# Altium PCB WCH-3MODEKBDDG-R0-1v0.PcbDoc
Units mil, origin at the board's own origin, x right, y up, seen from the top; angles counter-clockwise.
Board outline 452.76 x 645.67 mil, 2 copper layers (Top Layer, Bottom Layer); 13 components, 13 nets, 62 pads, 34 vias.
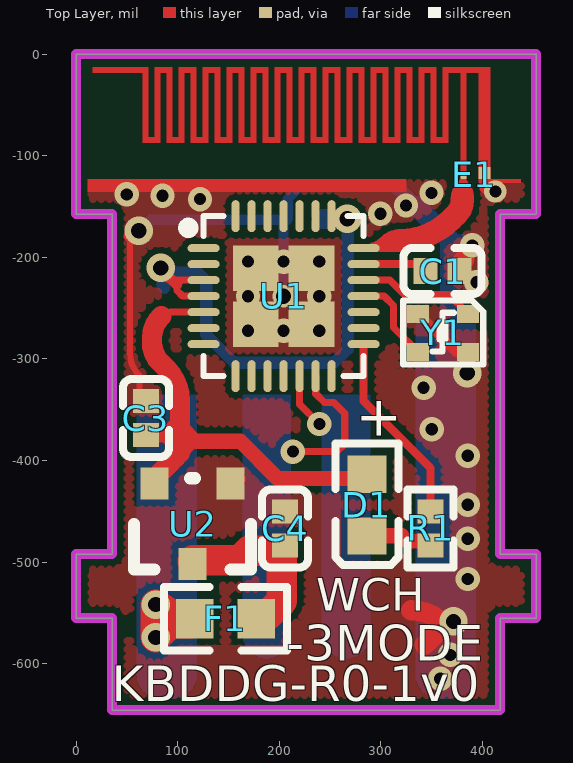
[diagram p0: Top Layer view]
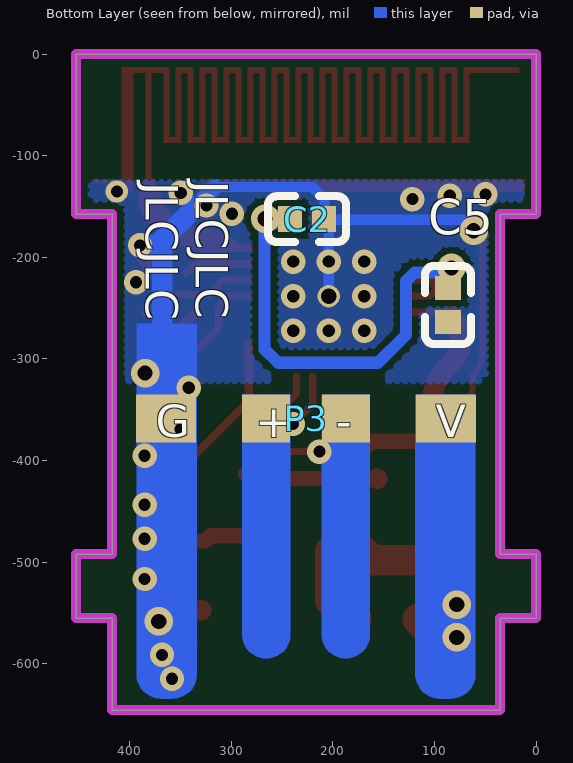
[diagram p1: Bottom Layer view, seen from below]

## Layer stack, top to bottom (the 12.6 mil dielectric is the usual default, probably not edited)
Top Solder: solder mask 0.4, Solder Resist, Dk 3.5
Top Layer: signal copper 1.4
Dielectric1: dielectric 12.6, FR-4, Dk 4.8
Bottom Layer: signal copper 1.4
Bottom Solder: solder mask 0.4, Solder Resist, Dk 3.5

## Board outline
0,-555.12 35.43,-555.12 35.43,-645.67 417.32,-645.67 417.32,-555.12 452.76,-555.12 452.76,-492.13 417.32,-492.13 417.32,-157.48 452.76,-157.48 452.76,0 0,0 0,-157.48 35.43,-157.48 35.43,-492.13 0,-492.13

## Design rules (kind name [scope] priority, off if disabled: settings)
Clearance [All] p1: gap=6 ignorepadtopadclearanceinfootprint=FALSE
ComponentClearance [All] p1 off: gap=10 collisioncheckmode=3 verticalgap=10 showdistances=FALSE
DiffPairsRouting [All] p1: maxlimit=15 minlimit=6 mostfreqgap=8 toplayer_minwidth=6 toplayer_maxwidth=15 toplayer_prefwidth=8 bottomlayer_minwidth=6 bottomlayer_maxwidth=15 bottomlayer_prefwidth=8 maxuncoupledlength=500
MinimumSolderMaskSliver [All] p1 off: minsoldermaskwidth=10
PolygonConnect [All] p1: connectstyle=Direct reliefconductorwidth=10 reliefentries=4 polygonreliefangle="90 Angle" airgapwidth=10
RoutingVias [All] p1: holewidth=28 width=50 viastyle="Through Hole" minholewidth=12 minwidth=24 maxholewidth=28 maxwidth=50
SilkToSilkClearance [All] p1 off: silktosilkclearance=10
SilkToSolderMaskClearance SilkscreenOverComponentPads [IsPad] p1 off: minsilkscreentomaskgap=10 clearancetoexposedcopper=TRUE
SolderMaskExpansion [All] p1: expansion=4 istentingtop=FALSE
Width [All] p1: maxlimit=50 minlimit=5.9 preferedwidth=10
25 further rules are at their usual default settings.

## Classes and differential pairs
differential pair NewDifferentialPair1: +PB10 -PB11

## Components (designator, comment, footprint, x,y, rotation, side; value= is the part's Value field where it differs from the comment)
C1 "2.2uF" 0402_C 377.43,-213.46 r270 top
C2 "0.1uF" 0402_C 208.8,-162.4 r270 bottom
C3 "0.1uF" 0402_C 68.7,-341.48 r0 top
C4 "2.2uF" 0402_C 205.58,-450.09 r0 top value=100pF
C5 "0.1uF" 0402_C 86.67,-230.11 r180 bottom
D1 "LED" 0603+ 286.15,-413.49 r270 top
E1 "ANTENNA" ANT-F-1-2.4G-0.8 381.31,-120.06 r180 top
F1 "500mA" 0603 116.65,-555.7 r0 top
P3 "USB" USBAM-4P 226.38,-358.45 r180 bottom
R1 "1K" 0402 348.83,-483.55 r90 top
U1 "CH582F" QFN28_4X4 204.17,-238.2 r270 top
U2 "CE6219 3V3" sot-23 152.07,-422.35 r180 top
Y1 "32M" 32M_2x1.6 385.64,-255.56 r180 top

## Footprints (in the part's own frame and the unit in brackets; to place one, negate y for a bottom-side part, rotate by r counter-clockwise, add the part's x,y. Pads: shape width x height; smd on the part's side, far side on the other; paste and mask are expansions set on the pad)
32M_2x1.6 [mm]
  rect 0.55x0.45 smd: 1(0,0) 2(1.25,0) 3(1.25,0.95) 4(0,0.95)
  silkscreen extent -0.38,-0.33 1.62,1.27
0402 [mm]
  rect 0.6x0.65 smd mask+0.051: 1(0,0) 2(0.85,0)
  silkscreen extent -0.55,-0.58 1.4,0.57
0402_C [mm]
  rect 0.65x0.6 smd mask+0.051: 1(0,0) 2(0,-0.85)
  silkscreen extent -0.58,-1.4 0.57,0.55
0603 [mm]
  rect 0.93x0.98 smd: 1(0,0) 2(1.54,0)
  silkscreen extent -0.76,-0.79 2.3,0.79
0603+ [mm]
  rect 0.93x0.98 smd: 1(0,0) 2(1.54,0)
  silkscreen extent -0.76,-0.79 2.27,0.79
ANT-F-1-2.4G-0.8 [mm]
  rect 0.3x0.3 smd mask+0: 0(-0.525,-0.075)
  rect 0.15x0.15 smd mask+0: 1(0,0)
  Top Layer region: -0.675,-2.725 -0.375,-2.725 -0.375,0.075 -0.675,0.075
  Top Layer region: -0.075,-2.725 0.075,-2.725 0.075,0.075 -0.075,0.075
  Top Layer region: -0.675,-2.575 -0.675,-2.725 0.075,-2.725 0.075,-2.575
  Top Layer region: 0.375,-2.725 0.525,-2.725 0.525,-0.825 0.375,-0.825
  Top Layer region: 0.675,-2.725 0.825,-2.725 0.825,-0.825 0.675,-0.825
  Top Layer region: 0.975,-2.725 1.125,-2.725 1.125,-0.825 0.975,-0.825
  Top Layer region: 1.275,-2.725 1.425,-2.725 1.425,-0.825 1.275,-0.825
  Top Layer region: 1.575,-2.725 1.725,-2.725 1.725,-0.825 1.575,-0.825
  Top Layer region: 0.075,-2.725 0.525,-2.725 0.525,-2.575 0.075,-2.575
  Top Layer region: 0.675,-2.725 1.125,-2.725 1.125,-2.575 0.675,-2.575
  Top Layer region: 1.275,-2.725 1.725,-2.725 1.725,-2.575 1.275,-2.575
  Top Layer region: 0.375,-0.975 0.825,-0.975 0.825,-0.825 0.375,-0.825
  Top Layer region: 0.975,-0.975 1.425,-0.975 1.425,-0.825 0.975,-0.825
  Top Layer region: 2.175,-0.975 2.625,-0.975 2.625,-0.825 2.175,-0.825
  Top Layer region: 1.575,-0.975 2.025,-0.975 2.025,-0.825 1.575,-0.825
  Top Layer region: 2.475,-2.725 2.925,-2.725 2.925,-2.575 2.475,-2.575
  Top Layer region: 1.875,-2.725 2.325,-2.725 2.325,-2.575 1.875,-2.575
  Top Layer region: 2.775,-2.725 2.925,-2.725 2.925,-0.825 2.775,-0.825
  Top Layer region: 2.475,-2.725 2.625,-2.725 2.625,-0.825 2.475,-0.825
  Top Layer region: 2.175,-2.725 2.325,-2.725 2.325,-0.825 2.175,-0.825
  Top Layer region: 1.875,-2.725 2.025,-2.725 2.025,-0.825 1.875,-0.825
  Top Layer region: 3.375,-0.975 3.825,-0.975 3.825,-0.825 3.375,-0.825
  Top Layer region: 2.775,-0.975 3.225,-0.975 3.225,-0.825 2.775,-0.825
  Top Layer region: 3.675,-2.725 4.125,-2.725 4.125,-2.575 3.675,-2.575
  Top Layer region: 3.075,-2.725 3.525,-2.725 3.525,-2.575 3.075,-2.575
  Top Layer region: 3.975,-2.725 4.125,-2.725 4.125,-0.825 3.975,-0.825
  Top Layer region: 3.675,-2.725 3.825,-2.725 3.825,-0.825 3.675,-0.825
  Top Layer region: 3.375,-2.725 3.525,-2.725 3.525,-0.825 3.375,-0.825
  Top Layer region: 3.075,-2.725 3.225,-2.725 3.225,-0.825 3.075,-0.825
  Top Layer region: 4.575,-0.975 5.025,-0.975 5.025,-0.825 4.575,-0.825
  Top Layer region: 3.975,-0.975 4.425,-0.975 4.425,-0.825 3.975,-0.825
  Top Layer region: 4.875,-2.725 5.325,-2.725 5.325,-2.575 4.875,-2.575
  Top Layer region: 4.275,-2.725 4.725,-2.725 4.725,-2.575 4.275,-2.575
  Top Layer region: 5.175,-2.725 5.325,-2.725 5.325,-0.825 5.175,-0.825
  Top Layer region: 4.875,-2.725 5.025,-2.725 5.025,-0.825 4.875,-0.825
  Top Layer region: 4.575,-2.725 4.725,-2.725 4.725,-0.825 4.575,-0.825
  Top Layer region: 4.275,-2.725 4.425,-2.725 4.425,-0.825 4.275,-0.825
  Top Layer region: 5.775,-0.975 6.225,-0.975 6.225,-0.825 5.775,-0.825
  Top Layer region: 5.175,-0.975 5.625,-0.975 5.625,-0.825 5.175,-0.825
  Top Layer region: 6.075,-2.725 6.525,-2.725 6.525,-2.575 6.075,-2.575
  Top Layer region: 5.475,-2.725 5.925,-2.725 5.925,-2.575 5.475,-2.575
  Top Layer region: 6.375,-2.725 6.525,-2.725 6.525,-0.825 6.375,-0.825
  Top Layer region: 6.075,-2.725 6.225,-2.725 6.225,-0.825 6.075,-0.825
  Top Layer region: 5.775,-2.725 5.925,-2.725 5.925,-0.825 5.775,-0.825
  Top Layer region: 5.475,-2.725 5.625,-2.725 5.625,-0.825 5.475,-0.825
  Top Layer region: 6.975,-0.975 7.425,-0.975 7.425,-0.825 6.975,-0.825
  Top Layer region: 6.375,-0.975 6.825,-0.975 6.825,-0.825 6.375,-0.825
  Top Layer region: 7.275,-2.725 7.725,-2.725 7.725,-2.575 7.275,-2.575
  Top Layer region: 6.675,-2.725 7.125,-2.725 7.125,-2.575 6.675,-2.575
  Top Layer region: 7.575,-2.725 7.725,-2.725 7.725,-0.825 7.575,-0.825
  Top Layer region: 7.275,-2.725 7.425,-2.725 7.425,-0.825 7.275,-0.825
  Top Layer region: 6.975,-2.725 7.125,-2.725 7.125,-0.825 6.975,-0.825
  Top Layer region: 6.675,-2.725 6.825,-2.725 6.825,-0.825 6.675,-0.825
  Top Layer region: 7.575,-0.975 8.025,-0.975 8.025,-0.825 7.575,-0.825
  Top Layer region: 7.875,-2.725 9.275,-2.725 9.275,-2.575 7.875,-2.575
  Top Layer region: 7.875,-2.725 8.025,-2.725 8.025,-0.825 7.875,-0.825
QFN28_4X4 [mm]
  rect 1.143x1.143 smd mask+0: 0(-0.699,0.698) 0(-0.698,-0.699) 0(0.698,0.698) 0(0.699,-0.699)
  round 0.559 hole 0.381 mask+0.102: 0(0,0)
  oval 0.2x0.8 smd: 1(-1.2,-2) 2(-0.8,-2) 3(-0.4,-2) 4(0,-2) 5(0.4,-2) 6(0.8,-2) 7(1.2,-2) 15(1.2,2) 16(0.8,2) 17(0.4,2) 18(0,2) 19(-0.4,2) 20(-0.8,2) 21(-1.2,2)
  oval 0.8x0.2 smd: 8(2,-1.2) 9(2,-0.8) 10(2,-0.4) 11(2,0) 12(2,0.4) 13(2,0.8) 14(2,1.2) 22(-2,1.2) 23(-2,0.8) 24(-2,0.4) 25(-2,0) 26(-2,-0.4) 27(-2,-0.8) 28(-2,-1.2)
  silkscreen extent -2,-2.51 2,2
sot-23 [mm]
  rect 0.7x0.8 smd: 1(0,0) 2(1.9,0) 3(0.95,2.02)
  silkscreen extent -0.51,-0.13 2.41,2.16
USBAM-4P [mm]
  rect 1.5x1.2 smd: 1(3.5,0) 4(-3.5,0)
  rect 1.2x1.2 smd: 2(1,0) 3(-1,0)
  Top Layer region: -0.998,-6.006 -1.227,-5.959 -1.422,-5.829 -1.551,-5.634 -1.596,-5.404 -1.596,-5.404 -1.596,-5.404 -1.596,0.594 -0.396,0.594 -0.396,-5.404 -0.396,-5.404 -0.441,-5.634 -0.571,-5.829 -0.765,-5.959 -0.995,-6.006
  Top Layer region: -3.639,-7.006 -3.868,-6.959 -4.062,-6.829 -4.192,-6.634 -4.237,-6.404 -4.237,-6.404 -4.237,-6.404 -4.237,0.594 -2.737,0.594 -2.737,-6.404 -2.737,-6.404 -2.782,-6.634 -2.911,-6.829 -3.106,-6.959 -3.335,-7.006 -3.335,-7.006
  Top Layer region: 0.989,-6.006 0.759,-5.959 0.565,-5.829 0.436,-5.634 0.39,-5.404 0.39,-5.404 0.39,-5.404 0.39,0.594 1.591,0.594 1.591,-5.404 1.591,-5.404 1.546,-5.634 1.416,-5.829 1.222,-5.959 0.992,-6.006
  Top Layer region: 3.331,-7.006 3.102,-6.959 2.907,-6.829 2.778,-6.634 2.733,-6.404 2.733,-6.404 2.733,-6.404 2.733,0.594 4.233,0.594 4.233,-6.404 4.233,-6.404 4.188,-6.634 4.058,-6.829 3.864,-6.959 3.634,-7.006 3.634,-7.006
  Top Layer region: -4.233,0.42

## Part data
C1: library part C0402
C2 C3 C5: library part CAP, "Capacitor"
C4: library part Cap, "Capacitor"
E1: "Generic Antenna"
F1: library part FAF-0031.37xx, "Fuse holder"
R1: library part RES2
U1: "RISC-V MCU with BLE/2*USB/ADC/PWM/SPI/I2C/4*UART"
Y1: library part XTAL, "Crystal Oscillator"

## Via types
v1: diameter 24, hole 12, Top Layer to Bottom Layer, tented both sides, 20 vias
v2: diameter 28, hole 15, Top Layer to Bottom Layer, tented both sides, 7 vias
v3: diameter 24, hole 12, Top Layer to Bottom Layer, 6 vias
v4: diameter 22, hole 12, Top Layer to Bottom Layer, tented both sides, 1 vias

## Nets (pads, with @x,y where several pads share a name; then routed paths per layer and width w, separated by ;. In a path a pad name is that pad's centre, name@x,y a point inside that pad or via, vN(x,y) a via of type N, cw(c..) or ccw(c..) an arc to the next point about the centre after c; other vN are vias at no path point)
+3V3: C3.2 D1.1 U1.5 U2.2 | length 562
  Top Layer w7: 83.85,-257.88 84.55,-257.18 cw(c92.36,-264.99) 92.36,-253.95 U1.5
  Top Layer w15: C3.2 88.46,-374.94 ; 92.57,-402.07 96.1,-398.54 96.1,-382.58 ; D1.1 281.93,-417.71 198.3,-417.71 161.6,-381 117.17,-381 ; 88.46,-374.94 96.1,-382.58 ; 88.46,-374.94 96.1,-374.94 ; 88.46,-374.94 102.16,-361.24 102.16,-366 117.17,-381 ; 96.1,-382.58 96.1,-374.94 ; 96.1,-382.58 102.16,-388.64 102.16,-392.48 113.64,-381 ; 96.1,-374.94 102.16,-381 113.64,-381 ; 113.64,-381 117.17,-381
  Top Layer w20: U2.2@77.27,-419.35 77.27,-417.38 92.57,-402.07 ; 83.85,-257.88 83.2,-258.53 ccw(c103.73,-279.06) 74.7,-279.06 74.7,-283.97 ccw(c102.27,-283.97) 82.77,-303.47 89,-309.7 cw(c57.22,-341.48) 102.16,-341.48 102.16,-361.24 ; 96.1,-398.54 102.16,-392.48 ; 102.16,-388.64 102.16,-381 102.16,-366
+5V: F1.1 P3.1 | length 126.9
  Top Layer w30: v2@81.43,-544.89 v2(78.26,-541.71) ; v2(78.26,-541.71) 92.79,-550.79 104.97,-558.4 F1.1 116.65,-556.68 113.35,-559.99 92.32,-559.99 v2(78.26,-574.06) v2(78.26,-541.71)
GND: C1.1 C2.1 C3.1 C4.1 C5.2 E1.0 P3.4 U1.0 U2.1 Y1.2 Y1.4 | length 1110.2
  Top Layer w6: v2@59.4,-171.51 ccw(c74.92,-186.99) 53.01,-186.99 53.01,-294.31 ccw(c84.48,-294.31) 62.22,-316.57 62.22,-325.84 ccw(c84.33,-325.84) C3.1
  Top Layer w10: v2@51.43,-179.49 59.4,-171.51 v2@63.92,-167 ; Y1.2 373.83,-292.96 Y1.4 ; 401.98,-132.06 E1.0@401.98,-112.1
  Top Layer w20: U2.1@156.26,-417.89 U2.1@156.46,-418.1 ; 329.58,-547.42 cw(c329.58,-594.42) 362.82,-561.19 342.86,-581.14 ; C1.1 cw(c393.85,-213.46) C1.1@382.24,-201.85
  Bottom Layer w10: v2(61.64,-173.7) 72.3,-163.04 C2.1@206.67,-163.04 ; U1.0@204.17,-238.2 204.17,-166.41 208.18,-162.4 208.18,-142.57 219.88,-130.88 316.04,-130.88
  Bottom Layer w15: 316.04,-130.88 v1@334.73,-149.56
  Bottom Layer w20: v1@334.73,-149.56 368.11,-182.94 368.11,-199.43 ; 368.11,-485.81 368.11,-199.43 ; v1@380.65,-186.89 368.11,-199.43
  other v1: 358.4,-614.76 368.29,-591.24 385.42,-516.59 385.42,-476.88 169.17,-272.2 204.17,-272.2 239.17,-272.2 169.17,-238.2 239.17,-238.2 393.89,-224.42 169.17,-204.2 204.17,-204.2 239.17,-204.2 389.89,-188.23 299.46,-157.14 324.61,-148.96 121.86,-142.69 84.96,-139.43 49.84,-137.99 349.75,-136.54
  other v2: 371.42,-558.3 384.96,-313.89
  other v3: 385.42,-443.48 385.42,-395.2 349.92,-369.22 342,-328.32
  other v4: 412.66,-135.14
LED: R1.2 U1.15 | length 191.9
  Top Layer w8: U1.15 282.91,-341.53 348.83,-407.45 R1.2
NetC4_2: C4.2 F1.2 U2.3 | length 174.7
  Top Layer w30: U2.3@114.67,-498.87 115.42,-498.13 160.89,-498.13 170.29,-488.72 202.58,-488.72 202.58,-538.23 189.4,-551.41 180.59,-551.41 177.28,-554.72 F1.2
NetD1_2: D1.2 R1.1 | length 66.6
  Top Layer w15: D1.2 320.44,-474.12 325.56,-479.24 344.52,-479.24 R1.1
NetE1_1: E1.1 U1.21 | length 263.6
  Top Layer w5.91: 371.62,-143.73 371.62,-141.86 cw(c389.36,-141.86) 376.82,-129.32 377.94,-128.2 ; 376.78,-136.85 ccw(c374,-134.06) 377.94,-134.06 377.94,-129.32 377.94,-128.2 ; 379.54,-137.92 ccw(c375.28,-133.65) 381.31,-133.65 381.31,-128.43 E1.1@381.31,-122.24 ; 388.45,-143.04 388.45,-139.46 ccw(c372.84,-139.46) 383.87,-128.43 cw(c390.06,-122.24) E1.1@381.31,-122.24 ; 377.94,-128.2 ccw(c369.79,-120.06) E1.1 E1.1@381.31,-122.24
  Top Layer w8: U1.21 U1.21@283.17,-190.96 ; 314.75,-183.03 cw(c295.6,-163.87) U1.21@295.6,-190.96 ; 319.7,-176.33 318.48,-176.33 ccw(c318.48,-198.69) 302.67,-182.88 cw(c283.17,-163.38) U1.21@283.17,-190.96 ; 328.72,-185.79 cw(c316.24,-173.31) 316.24,-190.96 U1.21@295.6,-190.96 ; U1.21@283.17,-190.96 U1.21@295.6,-190.96
  Top Layer w22.9: 318.8,-183.51 ccw(c318.8,-112.25) 369.18,-162.64 374.47,-157.35 ccw(c361.12,-144) 380,-144
PB10: P3.2 U1.13 | length 138.1
  Top Layer w7: v3(213.32,-391.17) 256.77,-391.17 264.38,-383.55 264.38,-353.65 253.59,-342.86 244.4,-342.86 235.83,-334.29 235.83,-317.11 U1.13
PB11: P3.3 U1.12 | length 55.2
  Top Layer w7: U1.12 219.92,-344.56 v3(239.39,-364.03)
VDCIA: C2.2 C5.1 U1.3 U1.4 U1.22 | length 577.9
  Top Layer w7: v2@87.49,-215.38 84.33,-215.38 91.41,-222.45 94.56,-222.45 103.77,-222.45 ; 101.47,-224.76 103.77,-222.45 ; U1.4 104.84,-238.2 99.17,-232.53 99.17,-227.06 103.77,-222.45 ; U1.3 103.77,-222.45 ; U1.22 257.01,-159.46 cw(c257.01,-172.25) v2@266.06,-163.21
  Top Layer w10: v2@87.49,-215.38 94.56,-222.45 99.17,-227.06
  Bottom Layer w12: v2(83.33,-210.38) 85,-212.05 85,-214.76 85,-228.44 C5.1 ; v2@86.32,-213.44 95.29,-213.44 96.61,-214.76 119.41,-214.76 127.97,-223.32 127.97,-276.09 155.64,-303.76 253.89,-303.76 267.3,-290.35 267.3,-162.53 v2(266.86,-162.09) 241.95,-162.09 C2.2@241.8,-162.24
  Bottom Layer w20: C2.2@241.8,-162.24 266.7,-162.24 v2(266.86,-162.09)
VINTA: C1.2 U1.20 | length 64.7
  Top Layer w7.87: U1.20 335.21,-206.71 C1.2@343.96,-215.46
X32MI: U1.19 Y1.1 | length 116.4
  Top Layer w7: U1.19 308.82,-222.45 323.12,-236.75 366.83,-236.75 Y1.1
X32MO: U1.18 Y1.3 | length 88.8
  Top Layer w7: U1.18 303.16,-238.2 312.43,-247.47 312.43,-268.96 Y1.3
pads on no net: U1.1 U1.2 U1.6 U1.7 U1.8 U1.9 U1.10 U1.11 U1.14 U1.16 U1.17 U1.23 U1.24 U1.25 U1.26 U1.27 U1.28

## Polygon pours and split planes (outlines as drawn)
GND on Bottom Layer "GND" (hatched 90Degree grid 8 track 8, remove dead copper, pour order 4): 0.7,-125.11 2.57,-127.01 456.31,-127.01 456.31,-658.54 453.51,-661.4 447.92,-655.68 0.7,-655.68 -2.09,-652.83
GND on Top Layer "GND" (hatched 90Degree grid 8 track 8, remove dead copper, pour order 3): 0.7,-125.11 2.57,-127.01 456.31,-127.01 456.31,-658.54 453.51,-661.4 447.92,-655.68 0.7,-655.68 -2.09,-652.83

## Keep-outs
Keep-Out Layer:
  the board outline again, w10

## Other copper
Top Layer:
  rectangle net GND: 11.19,-135.87 325.21,-123.01
  rectangle net GND: 396.07,-127.05 437.76,-123.01
Bottom Layer:
  rectangle net GND: 334,-406.22 393.36,-265.21
  pour cut-out: 415.36,-635.67 37.39,-635.67 cw(c37.39,-633.38) 35.77,-635 35.77,-321.12 412.22,-321.12

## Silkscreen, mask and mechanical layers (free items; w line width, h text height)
Top Overlay:
  text "WCH" at 236.31,-547.59 h32
  text "-3MODE" at 207.4,-596.8 h35
  text "KBDDG-R0-1v0" at 35.01,-636.91 h35
Bottom Overlay:
  text "JLCJLC" at 334.83,-124.81 h32 r90
  text "JLCJLC" at 384.44,-126.17 h32 r90
Bottom Solder:
  rectangle: 35.43,-645.67 417.32,-330.14
Mechanical 1:
  the board outline again, w10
